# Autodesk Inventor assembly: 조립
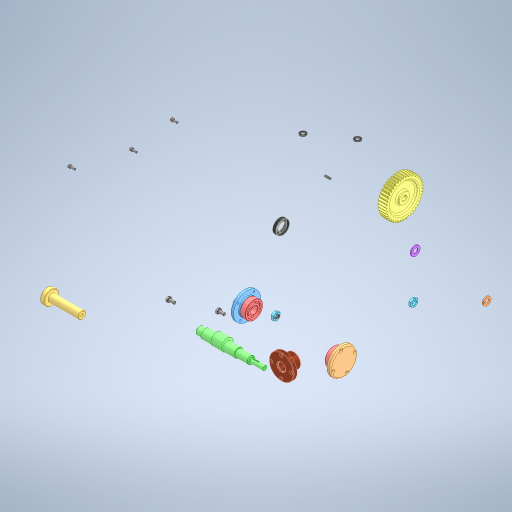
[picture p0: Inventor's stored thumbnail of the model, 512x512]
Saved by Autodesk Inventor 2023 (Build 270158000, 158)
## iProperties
Created: 2024-09
Part Number: 조립
Document SubType Name: Assembly
Designer: asung
Author: asung
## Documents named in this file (17)
- C:\Users\asung\Desktop\740904V1007\조립.iam
- C:\Users\asung\Desktop\740904V1007\깊은 홈 볼베어링 6203.ipt
- C:\Users\asung\Desktop\740904V1007\본체.ipt
- C:\Users\asung\Desktop\740904V1007\편심축.ipt
- C:\Users\asung\Desktop\740904V1007\앞커버.ipt
- C:\Users\asung\Desktop\740904V1007\뒷커버.ipt
- C:\Users\asung\Desktop\740904V1007\오일실 17 32 8.ipt
- C:\Users\asung\Desktop\740904V1007\육각 소켓 머리 볼트 M4x10.ipt
- C:\Users\asung\Desktop\740904V1007\평행키 3x3x14.ipt
- C:\Users\asung\Desktop\740904V1007\스퍼 기어.ipt
- C:\Users\asung\Desktop\740904V1007\평와셔 M10.ipt
- C:\Users\asung\Desktop\740904V1007\스프링와셔 M10.ipt
- C:\Users\asung\Desktop\740904V1007\육각 너트 M10x1.ipt
- C:\Users\asung\Desktop\740904V1007\로드.ipt
- C:\Users\asung\Desktop\740904V1007\부시.ipt
- C:\Users\asung\Desktop\740904V1007\실링 패드.ipt
- C:\Users\asung\Desktop\740904V1007\육각 머리 볼트 M6x0.75x12.ipt
